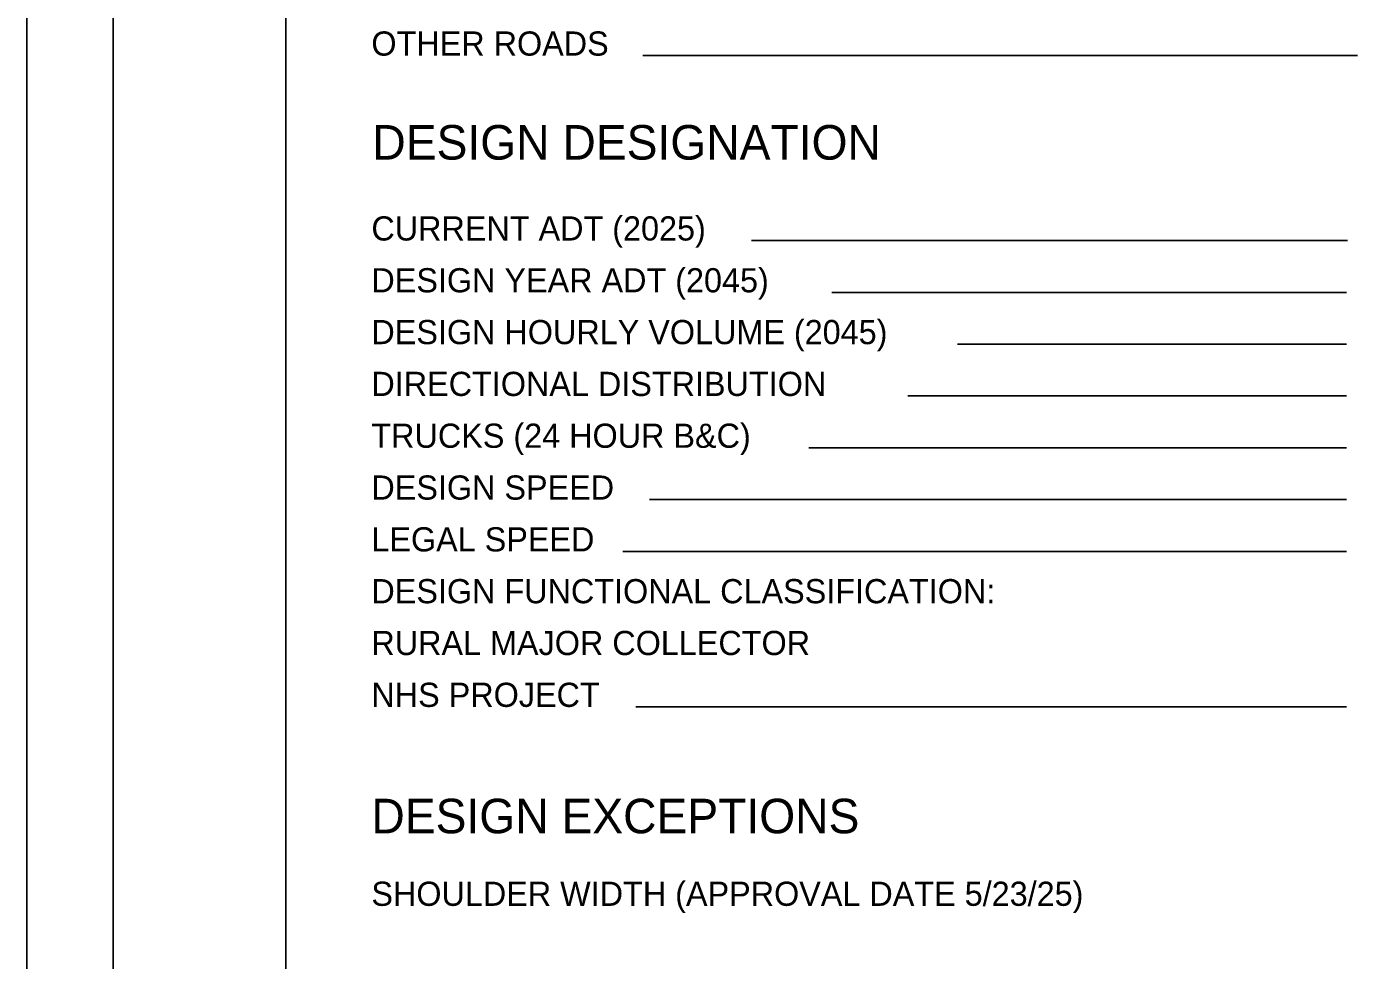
# Model space of a CAD drawing. Extents: x 0 to 34, y 0 to 22.
# Drawn here: x 0 to 7.72, y 5.64 to 11.04 of the extents above; entities that cross this region are included whole.
import ezdxf

# ---------------------------------------------------------------- set-up
doc = ezdxf.new("R2010")
doc.units = 0
for name, color, linetype in [('SH_Border', 7, 'Continuous'), ('SH_Cut_Line', 7, 'Continuous'), ('SH_Data', 7, 'Continuous'), ('SH_Text', 7, 'Continuous')]:
    doc.layers.add(name, color=color, linetype=linetype)

msp = doc.modelspace()

# ---------------------------------------------------------------- linework, layer by layer
at = {"layer": 'SH_Border'}
for points in [[(0.5, 21.5), (1.5, 21.5), (1.5, 0.5), (0.5, 0.5)], [(1.5, 21.5), (33.5, 21.5), (33.5, 0.5), (1.5, 0.5)]]:
    msp.add_lwpolyline(points, close=True, dxfattribs=at)
at = {"layer": 'SH_Cut_Line'}
msp.add_lwpolyline([(0, 0), (34, 0), (34, 22), (0, 22)], close=True, dxfattribs=at)
at = {"layer": 'SH_Data'}
for p, q in [((7.7, 10.8767), (3.5657, 10.8767)), ((7.6424, 9.8062), (4.1936, 9.8062)), ((7.6368, 9.5062), (4.6592, 9.5062)), ((7.6368, 9.2062), (5.3852, 9.2062)), ((7.6368, 8.9062), (5.0988, 8.9062)), ((7.6368, 8.6062), (4.5259, 8.6062)), ((7.6368, 8.3062), (3.6035, 8.3062)), ((7.6368, 8.0062), (3.4488, 8.0062)), ((7.6368, 7.1062), (3.5243, 7.1062))]:
    msp.add_line(p, q, dxfattribs=at)

# ---------------------------------------------------------------- texts
msp.add_text('DESIGN DESIGNATION', height=0.2, dxfattribs=at).set_placement((2, 10.2747))
at = {"layer": 'SH_Text'}
for s, height, p in [('OTHER ROADS', 0.14, (1.9944, 10.8767)), ('CURRENT ADT (2025)', 0.14, (1.9944, 9.8062)), ('DESIGN YEAR ADT (2045)', 0.14, (1.9944, 9.5062)), ('DESIGN HOURLY VOLUME (2045)', 0.14, (1.9944, 9.2062)), ('DIRECTIONAL DISTRIBUTION', 0.14, (1.9944, 8.9062)), ('TRUCKS (24 HOUR B&C)', 0.14, (1.9944, 8.6062)), ('DESIGN SPEED', 0.14, (1.9944, 8.3062)), ('LEGAL SPEED', 0.14, (1.9944, 8.0062)), ('DESIGN FUNCTIONAL CLASSIFICATION:', 0.14, (1.9944, 7.7062)), ('RURAL MAJOR COLLECTOR', 0.14, (1.9944, 7.4062)), ('NHS PROJECT', 0.14, (1.9944, 7.1062)), ('DESIGN EXCEPTIONS', 0.2, (1.9944, 6.3744)), ('SHOULDER WIDTH (APPROVAL DATE 5/23/25)', 0.14, (1.9944, 5.9544))]:
    msp.add_text(s, height=height, dxfattribs=at).set_placement(p)

doc.saveas('drawing.dxf')
